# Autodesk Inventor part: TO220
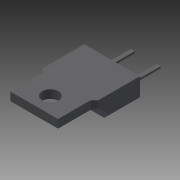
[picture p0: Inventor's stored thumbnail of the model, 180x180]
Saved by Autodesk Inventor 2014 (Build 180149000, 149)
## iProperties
Shininess: 64.0
Length Units: 11272
Angle Units: 11279
Time Units: 11290
Mass Units: 11286
Length Display Precision: 3
Angle Display Precision: 2
Compacted: True
Part Number: TO220
Document SubType Name: Modeling
Created: 2003-04
Designer: t_enrig
Manufacturer: Standard
Standards Organization: Custom
Density: 1 g/cm^3
Mass: 0.461056 g
Surface Area: 5.1489 cm^2
Volume: 0.461056 cm^3
Material: Generic
Appearance: TranslatedColorStyle
Density: 0.0
Volumn: 0.0
Area: 0.0
PropertySet Name: Model Information
Control State: 0
Master: False
Checked Out: False
Author: t_enrig
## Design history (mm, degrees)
feature "Base1"
body "Solid1"
